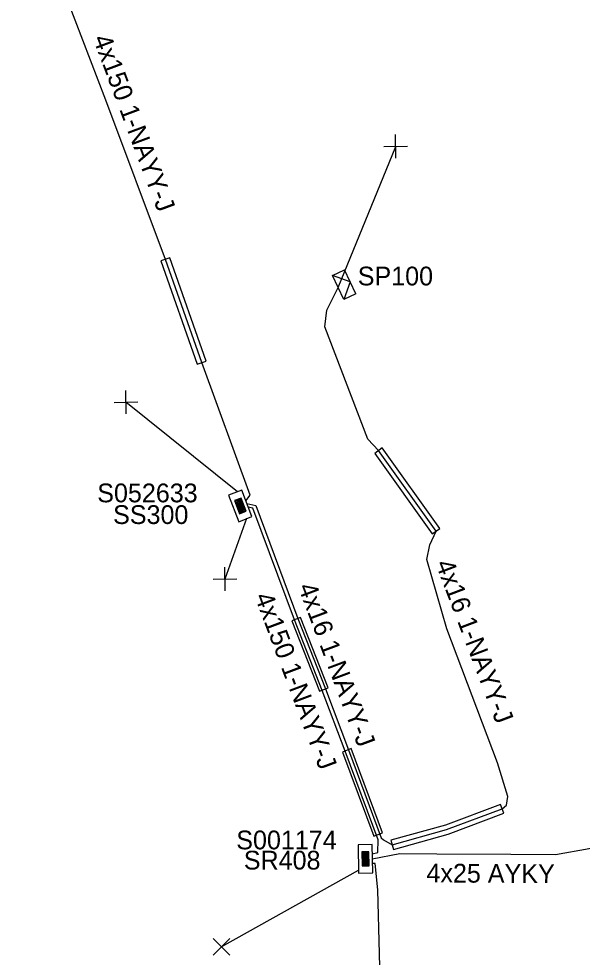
# Model space of a CAD drawing. Extents: x -762504 to -761250, y -1152974 to -1152253.
# Drawn here: x -761477.31 to -761447.44, y -1152514.18 to -1152464.42 of the extents above; entities that cross this region are included whole.
import ezdxf

# ---------------------------------------------------------------- set-up
doc = ezdxf.new("R2010")
doc.units = 0
for name, color, linetype in [('Vrstva 20', 7, 'Continuous'), ('Vrstva 28', 7, 'Continuous'), ('Vrstva 29', 7, 'Continuous'), ('Vrstva 30', 7, 'Continuous'), ('Vrstva 31', 7, 'Continuous'), ('Vrstva 33', 7, 'Continuous'), ('Vrstva 34', 7, 'Continuous'), ('Vrstva 5', 7, 'Continuous'), ('Vrstva 52', 7, 'Continuous'), ('Vrstva 54', 7, 'Continuous'), ('Vrstva 59', 7, 'Continuous'), ('Vrstva 6', 7, 'Continuous')]:
    doc.layers.add(name, color=color, linetype=linetype)

msp = doc.modelspace()

# ---------------------------------------------------------------- linework, layer by layer
at = {"layer": 'Vrstva 20'}
for points in [[(-761469.78, -1152477.26), (-761467.85, -1152482.73), (-761467.37, -1152482.57), (-761469.3, -1152477.1)], [(-761458.44, -1152487.47), (-761455.39, -1152491.74), (-761454.99, -1152491.45), (-761458.04, -1152487.18)], [(-761462.83, -1152496.35), (-761461.37, -1152500.08), (-761460.91, -1152499.9), (-761462.37, -1152496.17)], [(-761460.15, -1152503.3), (-761458.49, -1152507.77), (-761458.03, -1152507.59), (-761459.69, -1152503.12)], [(-761457.58, -1152507.98), (-761457.44, -1152508.46), (-761454.55, -1152507.65), (-761451.59, -1152506.54), (-761451.77, -1152506.08), (-761454.69, -1152507.17)]]:
    msp.add_lwpolyline(points, close=True, dxfattribs=at)
at = {"layer": 'Vrstva 28'}
for points in [[(-761465.485, -1152489.421), (-761466.185, -1152489.689)], [(-761464.947, -1152490.821), (-761465.485, -1152489.421)], [(-761466.185, -1152489.689), (-761465.648, -1152491.09)], [(-761465.523, -1152489.834), (-761465.875, -1152489.969)], [(-761465.55, -1152489.895), (-761465.814, -1152489.996)], [(-761465.317, -1152490.501), (-761465.55, -1152489.895)], [(-761465.256, -1152490.528), (-761465.523, -1152489.834)], [(-761465.875, -1152489.969), (-761465.609, -1152490.664)], [(-761465.814, -1152489.996), (-761465.582, -1152490.603)], [(-761465.577, -1152489.956), (-761465.753, -1152490.023)], [(-761465.753, -1152490.023), (-761465.554, -1152490.542)], [(-761465.604, -1152490.017), (-761465.692, -1152490.051)], [(-761465.692, -1152490.051), (-761465.527, -1152490.481)], [(-761465.633, -1152490.072), (-761465.498, -1152490.425)], [(-761465.439, -1152490.447), (-761465.604, -1152490.017)], [(-761465.378, -1152490.474), (-761465.577, -1152489.956)], [(-761465.648, -1152491.09), (-761464.947, -1152490.821)], [(-761465.609, -1152490.664), (-761465.256, -1152490.528)], [(-761465.582, -1152490.603), (-761465.317, -1152490.501)], [(-761465.554, -1152490.542), (-761465.378, -1152490.474)], [(-761465.527, -1152490.481), (-761465.439, -1152490.447)], [(-761458.57, -1152508.212), (-761459.319, -1152508.225)], [(-761459.319, -1152508.225), (-761459.293, -1152509.725)], [(-761458.543, -1152509.712), (-761458.57, -1152508.212)], [(-761458.746, -1152508.587), (-761459.124, -1152508.594)], [(-761459.124, -1152508.594), (-761459.111, -1152509.338)], [(-761458.793, -1152508.635), (-761459.076, -1152508.64)], [(-761459.076, -1152508.64), (-761459.065, -1152509.29)], [(-761458.839, -1152508.683), (-761459.028, -1152508.687)], [(-761459.028, -1152508.687), (-761459.018, -1152509.242)], [(-761458.885, -1152508.732), (-761458.98, -1152508.733)], [(-761458.98, -1152508.733), (-761458.972, -1152509.194)], [(-761458.932, -1152508.774), (-761458.925, -1152509.152)], [(-761458.877, -1152509.192), (-761458.885, -1152508.732)], [(-761458.829, -1152509.239), (-761458.839, -1152508.683)], [(-761458.781, -1152509.285), (-761458.793, -1152508.635)], [(-761458.733, -1152509.331), (-761458.746, -1152508.587)], [(-761459.111, -1152509.338), (-761458.733, -1152509.331)], [(-761459.065, -1152509.29), (-761458.781, -1152509.285)], [(-761459.018, -1152509.242), (-761458.829, -1152509.239)], [(-761458.972, -1152509.194), (-761458.877, -1152509.192)], [(-761459.293, -1152509.725), (-761458.543, -1152509.712)]]:
    msp.add_lwpolyline(points, dxfattribs=at)
at = {"layer": 'Vrstva 31'}
for points in [[(-761459.448, -1152479.011), (-761460.083, -1152479.306), (-761460.674, -1152478.038), (-761460.04, -1152477.742)], [(-761459.448, -1152479.011), (-761460.04, -1152477.742)], [(-761459.744, -1152478.376), (-761460.674, -1152478.038)], [(-761459.744, -1152478.376), (-761460.083, -1152479.306)]]:
    msp.add_lwpolyline(points, dxfattribs=at)
at = {"layer": 'Vrstva 34'}
for points in [[(-761457.319, -1152471.805), (-761457.341, -1152470.555)], [(-761457.955, -1152471.191), (-761456.705, -1152471.169)], [(-761471.619, -1152485.375), (-761471.641, -1152484.125)], [(-761472.255, -1152484.761), (-761471.005, -1152484.739)], [(-761466.369, -1152494.755), (-761466.391, -1152493.505)], [(-761467.005, -1152494.141), (-761465.755, -1152494.119)], [(-761467.002, -1152513.188), (-761466.118, -1152514.072)], [(-761467.002, -1152514.072), (-761466.118, -1152513.188)]]:
    msp.add_lwpolyline(points, dxfattribs=at)
at = {"layer": 'Vrstva 5'}
for points in [[(-761465.27, -1152489.98), (-761465.04, -1152489.69), (-761467.61, -1152482.65), (-761469.54, -1152477.18), (-761472.7, -1152468.73), (-761474.72, -1152463.41), (-761474.86, -1152462.7), (-761474.98, -1152462.21), (-761475.94, -1152459.34), (-761476.1, -1152459.17), (-761476.95, -1152457.19), (-761477.17, -1152456.57), (-761477.31, -1152456.52)], [(-761458.57, -1152508.7), (-761458.27, -1152508.63), (-761458.26, -1152507.96), (-761460.01, -1152503.25), (-761461.23, -1152500.03), (-761462.69, -1152496.3), (-761464.91, -1152490.37), (-761465.15, -1152490.32)], [(-761458.57, -1152508.96), (-761457.11, -1152508.68), (-761455.14, -1152508.7), (-761451.22, -1152508.72), (-761448.85, -1152508.73), (-761447.08, -1152508.42), (-761446.02, -1152508.12)], [(-761459.07, -1152530.24), (-761458.47, -1152529.97), (-761458.06, -1152525.95), (-761458.07, -1152520.54), (-761458.09, -1152517.4), (-761458.27, -1152510.61), (-761458.42, -1152509.21), (-761458.57, -1152509.21)]]:
    msp.add_lwpolyline(points, dxfattribs=at)
at = {"layer": 'Vrstva 52'}
msp.add_lwpolyline([(-761465.22, -1152490.12), (-761464.75, -1152490.23), (-761462.51, -1152496.22), (-761461.05, -1152499.95), (-761459.83, -1152503.18), (-761458.09, -1152507.85), (-761457.98, -1152507.96), (-761457.51, -1152508.22), (-761454.63, -1152507.41), (-761451.68, -1152506.31), (-761451.46, -1152506.11), (-761451.38, -1152505.65), (-761451.93, -1152503.87), (-761454.62, -1152496.77), (-761455.67, -1152493.09), (-761455.52, -1152492.32), (-761455.19, -1152491.59), (-761458.24, -1152487.32), (-761458.81, -1152486.72), (-761461.08, -1152480.76), (-761460.98, -1152479.88), (-761460.38, -1152478.67)], dxfattribs=at)
at = {"layer": 'Vrstva 59'}
for points in [[(-761460.38, -1152478.67), (-761457.33, -1152471.19)], [(-761465.72, -1152489.51), (-761471.63, -1152484.75)], [(-761465.23, -1152490.92), (-761466.38, -1152494.13)], [(-761459.31, -1152509.58), (-761466.56, -1152513.63)]]:
    msp.add_lwpolyline(points, dxfattribs=at)

# ---------------------------------------------------------------- texts
at = {"layer": 'Vrstva 29'}
for s, p in [('S052633', (-761473.15, -1152490.06)), ('S001174', (-761465.78, -1152508.46))]:
    msp.add_text(s, height=0.9943, dxfattribs=at).set_placement(p)
at = {"layer": 'Vrstva 30'}
for s, p in [('SS300', (-761472.31, -1152491.21)), ('SR408', (-761465.38, -1152509.53))]:
    msp.add_text(s, height=0.9943, dxfattribs=at).set_placement(p)
at = {"layer": 'Vrstva 33'}
msp.add_text('SP100', height=0.9943, dxfattribs=at).set_placement((-761459.34, -1152478.56))
at = {"layer": 'Vrstva 54'}
for rotation, p in [(290.7504, (-761455.23, -1152493.31)), (290.5121, (-761462.52, -1152494.54))]:
    msp.add_text('4x16 1-NAYY-J', height=0.99429, rotation=rotation, dxfattribs=at).set_placement(p)
at = {"layer": 'Vrstva 6'}
for s, height, rotation, p in [('4x150 1-NAYY-J', 0.99429, 290.504, (-761473.39, -1152465.47)), ('4x150 1-NAYY-J', 0.99429, 290.5157, (-761464.82, -1152495.05)), ('4x25 AYKY', 0.9943, 359.6698, (-761455.7, -1152510.21))]:
    msp.add_text(s, height=height, rotation=rotation, dxfattribs=at).set_placement(p)

doc.saveas('drawing.dxf')
